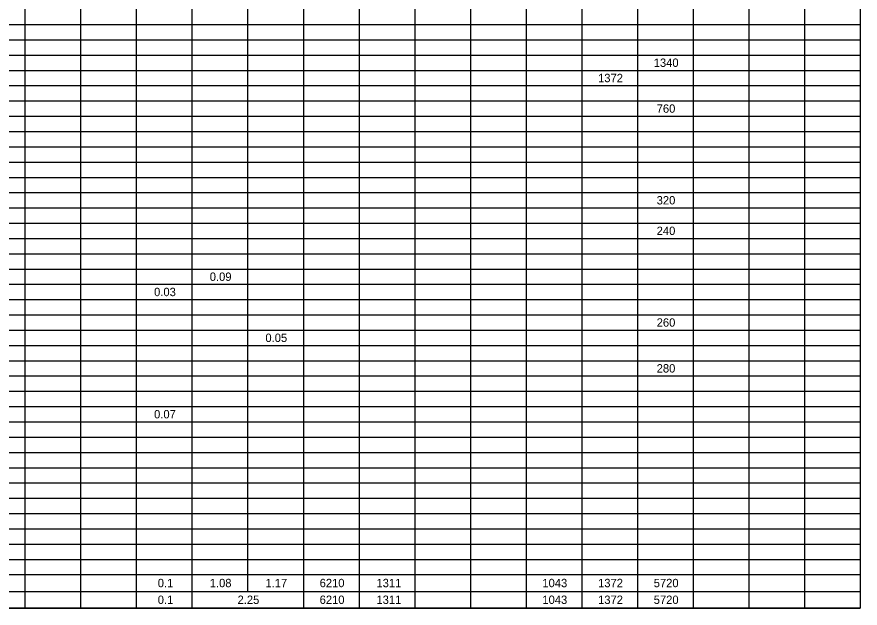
# Model space of a CAD drawing. Extents: x 91011267 to 91022583, y 37007614 to 37014266.
# Drawn here: x 91012044 to 91012802, y 37010175 to 37010707 of the extents above; entities that cross this region are included whole.
import ezdxf

# ---------------------------------------------------------------- set-up
doc = ezdxf.new("R2010")
doc.units = 0
doc.layers.add('SC_Scratch2', color=7, linetype='Continuous')
doc.layers.add('SH_Data', color=7, linetype='Continuous')

msp = doc.modelspace()

# ---------------------------------------------------------------- linework, layer by layer
at = {"layer": 'SC_Scratch2'}
msp.add_lwpolyline([(91011277.35, 37011225.45), (91012802.35, 37011225.45), (91012802.35, 37010175.45), (91011277.35, 37010175.45)], close=True, dxfattribs=at)
at = {"layer": 'SH_Data'}
for p, q in [((91012051.05, 37010851.25), (91012051.05, 37010645.17)), ((91012101.14, 37010851.25), (91012101.14, 37010645.17)), ((91012151.23, 37010851.25), (91012151.23, 37010645.17)), ((91012201.31, 37010851.25), (91012201.31, 37010645.17)), ((91012251.4, 37010851.25), (91012251.4, 37010645.17)), ((91012301.49, 37010851.25), (91012301.49, 37010645.17)), ((91012351.57, 37010851.25), (91012351.57, 37010645.17)), ((91012401.66, 37010851.25), (91012401.66, 37010645.17)), ((91012451.75, 37010851.25), (91012451.75, 37010645.17)), ((91012501.83, 37010851.25), (91012501.83, 37010645.17)), ((91012551.92, 37010851.25), (91012551.92, 37010645.17)), ((91012602, 37010851.25), (91012602, 37010645.17)), ((91012652.09, 37010851.25), (91012652.09, 37010645.17)), ((91012702.18, 37010851.25), (91012702.18, 37010645.17)), ((91012752.26, 37010851.25), (91012752.26, 37010645.17)), ((91012802.35, 37010851.25), (91012802.35, 37010645.17)), ((91012000.97, 37010700.13), (91012551.92, 37010700.13)), ((91012551.92, 37010700.13), (91012602, 37010700.13)), ((91012602, 37010700.13), (91012652.09, 37010700.13)), ((91012652.09, 37010700.13), (91012702.18, 37010700.13)), ((91012702.18, 37010700.13), (91012802.35, 37010700.13)), ((91012000.97, 37010686.39), (91012551.92, 37010686.39)), ((91012551.92, 37010686.39), (91012602, 37010686.39)), ((91012602, 37010686.39), (91012652.09, 37010686.39)), ((91012652.09, 37010686.39), (91012702.18, 37010686.39)), ((91012702.18, 37010686.39), (91012802.35, 37010686.39)), ((91012000.97, 37010672.65), (91012551.92, 37010672.65)), ((91012551.92, 37010672.65), (91012602, 37010672.65)), ((91012602, 37010672.65), (91012652.09, 37010672.65)), ((91012652.09, 37010672.65), (91012702.18, 37010672.65)), ((91012702.18, 37010672.65), (91012802.35, 37010672.65)), ((91012000.97, 37010658.91), (91012551.92, 37010658.91)), ((91012551.92, 37010658.91), (91012602, 37010658.91)), ((91012602, 37010658.91), (91012652.09, 37010658.91)), ((91012652.09, 37010658.91), (91012702.18, 37010658.91)), ((91012702.18, 37010658.91), (91012802.35, 37010658.91)), ((91012000.97, 37010645.17), (91012551.92, 37010645.17)), ((91012051.05, 37010645.17), (91012051.05, 37010631.43)), ((91012101.14, 37010645.17), (91012101.14, 37010631.43)), ((91012151.23, 37010645.17), (91012151.23, 37010631.43)), ((91012201.31, 37010645.17), (91012201.31, 37010631.43)), ((91012251.4, 37010645.17), (91012251.4, 37010631.43)), ((91012301.49, 37010645.17), (91012301.49, 37010631.43)), ((91012351.57, 37010645.17), (91012351.57, 37010631.43)), ((91012401.66, 37010645.17), (91012401.66, 37010631.43)), ((91012451.75, 37010645.17), (91012451.75, 37010631.43)), ((91012501.83, 37010645.17), (91012501.83, 37010631.43)), ((91012551.92, 37010645.17), (91012602, 37010645.17)), ((91012551.92, 37010645.17), (91012551.92, 37010631.43)), ((91012602, 37010645.17), (91012652.09, 37010645.17)), ((91012602, 37010645.17), (91012602, 37010631.43)), ((91012652.09, 37010645.17), (91012702.18, 37010645.17)), ((91012652.09, 37010645.17), (91012652.09, 37010631.43)), ((91012702.18, 37010645.17), (91012802.35, 37010645.17)), ((91012702.18, 37010645.17), (91012702.18, 37010631.43)), ((91012752.26, 37010645.17), (91012752.26, 37010631.43)), ((91012802.35, 37010645.17), (91012802.35, 37010631.43)), ((91012000.97, 37010631.43), (91012551.92, 37010631.43)), ((91012051.05, 37010631.43), (91012051.05, 37010617.7)), ((91012101.14, 37010631.43), (91012101.14, 37010617.7)), ((91012151.23, 37010631.43), (91012151.23, 37010617.7)), ((91012201.31, 37010631.43), (91012201.31, 37010617.7)), ((91012251.4, 37010631.43), (91012251.4, 37010617.7)), ((91012301.49, 37010631.43), (91012301.49, 37010617.7)), ((91012351.57, 37010631.43), (91012351.57, 37010617.7)), ((91012401.66, 37010631.43), (91012401.66, 37010617.7)), ((91012451.75, 37010631.43), (91012451.75, 37010617.7)), ((91012501.83, 37010631.43), (91012501.83, 37010617.7)), ((91012551.92, 37010631.43), (91012602, 37010631.43)), ((91012551.92, 37010631.43), (91012551.92, 37010617.7)), ((91012602, 37010631.43), (91012652.09, 37010631.43)), ((91012602, 37010631.43), (91012602, 37010617.7)), ((91012652.09, 37010631.43), (91012702.18, 37010631.43)), ((91012652.09, 37010631.43), (91012652.09, 37010617.7)), ((91012702.18, 37010631.43), (91012802.35, 37010631.43)), ((91012702.18, 37010631.43), (91012702.18, 37010617.7)), ((91012752.26, 37010631.43), (91012752.26, 37010617.7)), ((91012802.35, 37010631.43), (91012802.35, 37010617.7)), ((91012000.97, 37010617.7), (91012551.92, 37010617.7)), ((91012051.05, 37010617.7), (91012051.05, 37010576.48)), ((91012101.14, 37010617.7), (91012101.14, 37010576.48)), ((91012151.23, 37010617.7), (91012151.23, 37010576.48)), ((91012201.31, 37010617.7), (91012201.31, 37010576.48)), ((91012251.4, 37010617.7), (91012251.4, 37010576.48)), ((91012301.49, 37010617.7), (91012301.49, 37010576.48)), ((91012351.57, 37010617.7), (91012351.57, 37010576.48)), ((91012401.66, 37010617.7), (91012401.66, 37010576.48)), ((91012451.75, 37010617.7), (91012451.75, 37010576.48)), ((91012501.83, 37010617.7), (91012501.83, 37010576.48)), ((91012551.92, 37010617.7), (91012602, 37010617.7)), ((91012551.92, 37010617.7), (91012551.92, 37010576.48)), ((91012602, 37010617.7), (91012652.09, 37010617.7)), ((91012602, 37010617.7), (91012602, 37010576.48)), ((91012652.09, 37010617.7), (91012702.18, 37010617.7)), ((91012652.09, 37010617.7), (91012652.09, 37010576.48)), ((91012702.18, 37010617.7), (91012802.35, 37010617.7)), ((91012702.18, 37010617.7), (91012702.18, 37010576.48)), ((91012752.26, 37010617.7), (91012752.26, 37010576.48)), ((91012802.35, 37010617.7), (91012802.35, 37010576.48)), ((91012000.97, 37010603.96), (91012551.92, 37010603.96)), ((91012551.92, 37010603.96), (91012602, 37010603.96)), ((91012602, 37010603.96), (91012652.09, 37010603.96)), ((91012652.09, 37010603.96), (91012702.18, 37010603.96)), ((91012702.18, 37010603.96), (91012802.35, 37010603.96)), ((91012000.97, 37010590.22), (91012551.92, 37010590.22)), ((91012551.92, 37010590.22), (91012602, 37010590.22)), ((91012602, 37010590.22), (91012652.09, 37010590.22)), ((91012652.09, 37010590.22), (91012702.18, 37010590.22)), ((91012702.18, 37010590.22), (91012802.35, 37010590.22)), ((91012000.97, 37010576.48), (91012551.92, 37010576.48)), ((91012051.05, 37010576.48), (91012051.05, 37010562.74)), ((91012101.14, 37010576.48), (91012101.14, 37010562.74)), ((91012151.23, 37010576.48), (91012151.23, 37010562.74)), ((91012201.31, 37010576.48), (91012201.31, 37010562.74)), ((91012251.4, 37010576.48), (91012251.4, 37010562.74)), ((91012301.49, 37010576.48), (91012301.49, 37010562.74)), ((91012351.57, 37010576.48), (91012351.57, 37010562.74)), ((91012401.66, 37010576.48), (91012401.66, 37010562.74)), ((91012451.75, 37010576.48), (91012451.75, 37010562.74)), ((91012501.83, 37010576.48), (91012501.83, 37010562.74)), ((91012551.92, 37010576.48), (91012602, 37010576.48)), ((91012551.92, 37010576.48), (91012551.92, 37010562.74)), ((91012602, 37010576.48), (91012652.09, 37010576.48)), ((91012602, 37010576.48), (91012602, 37010562.74)), ((91012652.09, 37010576.48), (91012702.18, 37010576.48)), ((91012652.09, 37010576.48), (91012652.09, 37010562.74)), ((91012702.18, 37010576.48), (91012802.35, 37010576.48)), ((91012702.18, 37010576.48), (91012702.18, 37010562.74)), ((91012752.26, 37010576.48), (91012752.26, 37010562.74)), ((91012802.35, 37010576.48), (91012802.35, 37010562.74)), ((91012000.97, 37010562.74), (91012551.92, 37010562.74)), ((91012051.05, 37010562.74), (91012051.05, 37010549)), ((91012101.14, 37010562.74), (91012101.14, 37010549)), ((91012151.23, 37010562.74), (91012151.23, 37010549)), ((91012201.31, 37010562.74), (91012201.31, 37010549)), ((91012251.4, 37010562.74), (91012251.4, 37010549)), ((91012301.49, 37010562.74), (91012301.49, 37010549)), ((91012351.57, 37010562.74), (91012351.57, 37010549)), ((91012401.66, 37010562.74), (91012401.66, 37010549)), ((91012451.75, 37010562.74), (91012451.75, 37010549)), ((91012501.83, 37010562.74), (91012501.83, 37010549)), ((91012551.92, 37010562.74), (91012602, 37010562.74)), ((91012551.92, 37010562.74), (91012551.92, 37010549)), ((91012602, 37010562.74), (91012652.09, 37010562.74)), ((91012602, 37010562.74), (91012602, 37010549)), ((91012652.09, 37010562.74), (91012702.18, 37010562.74)), ((91012652.09, 37010562.74), (91012652.09, 37010549)), ((91012702.18, 37010562.74), (91012802.35, 37010562.74)), ((91012702.18, 37010562.74), (91012702.18, 37010549)), ((91012752.26, 37010562.74), (91012752.26, 37010549)), ((91012802.35, 37010562.74), (91012802.35, 37010549)), ((91012000.97, 37010549), (91012551.92, 37010549)), ((91012051.05, 37010549), (91012051.05, 37010507.79)), ((91012101.14, 37010549), (91012101.14, 37010507.79)), ((91012151.23, 37010549), (91012151.23, 37010507.79)), ((91012201.31, 37010549), (91012201.31, 37010507.79)), ((91012251.4, 37010549), (91012251.4, 37010507.79)), ((91012301.49, 37010549), (91012301.49, 37010507.79)), ((91012351.57, 37010549), (91012351.57, 37010507.79)), ((91012401.66, 37010549), (91012401.66, 37010507.79)), ((91012451.75, 37010549), (91012451.75, 37010507.79)), ((91012501.83, 37010549), (91012501.83, 37010507.79)), ((91012551.92, 37010549), (91012602, 37010549)), ((91012551.92, 37010549), (91012551.92, 37010507.79)), ((91012602, 37010549), (91012652.09, 37010549)), ((91012602, 37010549), (91012602, 37010507.79)), ((91012652.09, 37010549), (91012702.18, 37010549)), ((91012652.09, 37010549), (91012652.09, 37010507.79)), ((91012702.18, 37010549), (91012802.35, 37010549)), ((91012702.18, 37010549), (91012702.18, 37010507.79)), ((91012752.26, 37010549), (91012752.26, 37010507.79)), ((91012802.35, 37010549), (91012802.35, 37010507.79)), ((91012000.97, 37010535.27), (91012551.92, 37010535.27)), ((91012551.92, 37010535.27), (91012602, 37010535.27)), ((91012602, 37010535.27), (91012652.09, 37010535.27)), ((91012652.09, 37010535.27), (91012702.18, 37010535.27)), ((91012702.18, 37010535.27), (91012802.35, 37010535.27)), ((91012000.97, 37010521.53), (91012551.92, 37010521.53)), ((91012551.92, 37010521.53), (91012602, 37010521.53)), ((91012602, 37010521.53), (91012652.09, 37010521.53)), ((91012652.09, 37010521.53), (91012702.18, 37010521.53)), ((91012702.18, 37010521.53), (91012802.35, 37010521.53)), ((91012000.97, 37010507.79), (91012551.92, 37010507.79)), ((91012051.05, 37010507.79), (91012051.05, 37010494.05)), ((91012101.14, 37010507.79), (91012101.14, 37010494.05)), ((91012151.23, 37010507.79), (91012151.23, 37010494.05)), ((91012201.31, 37010507.79), (91012201.31, 37010494.05)), ((91012251.4, 37010507.79), (91012251.4, 37010494.05)), ((91012301.49, 37010507.79), (91012301.49, 37010494.05)), ((91012351.57, 37010507.79), (91012351.57, 37010494.05)), ((91012401.66, 37010507.79), (91012401.66, 37010494.05)), ((91012451.75, 37010507.79), (91012451.75, 37010494.05)), ((91012501.83, 37010507.79), (91012501.83, 37010494.05)), ((91012551.92, 37010507.79), (91012602, 37010507.79)), ((91012551.92, 37010507.79), (91012551.92, 37010494.05)), ((91012602, 37010507.79), (91012652.09, 37010507.79)), ((91012602, 37010507.79), (91012602, 37010494.05)), ((91012652.09, 37010507.79), (91012702.18, 37010507.79)), ((91012652.09, 37010507.79), (91012652.09, 37010494.05)), ((91012702.18, 37010507.79), (91012802.35, 37010507.79)), ((91012702.18, 37010507.79), (91012702.18, 37010494.05)), ((91012752.26, 37010507.79), (91012752.26, 37010494.05)), ((91012802.35, 37010507.79), (91012802.35, 37010494.05)), ((91012000.97, 37010494.05), (91012551.92, 37010494.05)), ((91012051.05, 37010494.05), (91012051.05, 37010480.31)), ((91012101.14, 37010494.05), (91012101.14, 37010480.31)), ((91012151.23, 37010494.05), (91012151.23, 37010480.31)), ((91012201.31, 37010494.05), (91012201.31, 37010480.31)), ((91012251.4, 37010494.05), (91012251.4, 37010480.31)), ((91012301.49, 37010494.05), (91012301.49, 37010480.31)), ((91012351.57, 37010494.05), (91012351.57, 37010480.31)), ((91012401.66, 37010494.05), (91012401.66, 37010480.31)), ((91012451.75, 37010494.05), (91012451.75, 37010480.31)), ((91012501.83, 37010494.05), (91012501.83, 37010480.31)), ((91012551.92, 37010494.05), (91012602, 37010494.05)), ((91012551.92, 37010494.05), (91012551.92, 37010480.31)), ((91012602, 37010494.05), (91012652.09, 37010494.05)), ((91012602, 37010494.05), (91012602, 37010480.31)), ((91012652.09, 37010494.05), (91012702.18, 37010494.05)), ((91012652.09, 37010494.05), (91012652.09, 37010480.31)), ((91012702.18, 37010494.05), (91012802.35, 37010494.05)), ((91012702.18, 37010494.05), (91012702.18, 37010480.31)), ((91012752.26, 37010494.05), (91012752.26, 37010480.31)), ((91012802.35, 37010494.05), (91012802.35, 37010480.31)), ((91012000.97, 37010480.31), (91012551.92, 37010480.31)), ((91012051.05, 37010480.31), (91012051.05, 37010175.45)), ((91012101.14, 37010480.31), (91012101.14, 37010175.45)), ((91012151.23, 37010480.31), (91012151.23, 37010175.45)), ((91012201.31, 37010480.31), (91012201.31, 37010175.45)), ((91012251.4, 37010480.31), (91012251.4, 37010190.5)), ((91012301.49, 37010480.31), (91012301.49, 37010175.45)), ((91012351.57, 37010480.31), (91012351.57, 37010175.45)), ((91012401.66, 37010480.31), (91012401.66, 37010175.45)), ((91012451.75, 37010480.31), (91012451.75, 37010175.45)), ((91012501.83, 37010480.31), (91012501.83, 37010175.45)), ((91012551.92, 37010480.31), (91012602, 37010480.31)), ((91012551.92, 37010480.31), (91012551.92, 37010175.45)), ((91012602, 37010480.31), (91012652.09, 37010480.31)), ((91012602, 37010480.31), (91012602, 37010175.45)), ((91012652.09, 37010480.31), (91012702.18, 37010480.31)), ((91012652.09, 37010480.31), (91012652.09, 37010175.45)), ((91012702.18, 37010480.31), (91012802.35, 37010480.31)), ((91012702.18, 37010480.31), (91012702.18, 37010175.45)), ((91012752.26, 37010480.31), (91012752.26, 37010175.45)), ((91012802.35, 37010480.31), (91012802.35, 37010175.45)), ((91012000.97, 37010466.57), (91012551.92, 37010466.57)), ((91012551.92, 37010466.57), (91012602, 37010466.57)), ((91012602, 37010466.57), (91012652.09, 37010466.57)), ((91012652.09, 37010466.57), (91012702.18, 37010466.57)), ((91012702.18, 37010466.57), (91012802.35, 37010466.57)), ((91012000.97, 37010452.84), (91012551.92, 37010452.84)), ((91012551.92, 37010452.84), (91012602, 37010452.84)), ((91012602, 37010452.84), (91012652.09, 37010452.84)), ((91012652.09, 37010452.84), (91012702.18, 37010452.84)), ((91012702.18, 37010452.84), (91012802.35, 37010452.84)), ((91012000.97, 37010439.1), (91012551.92, 37010439.1)), ((91012551.92, 37010439.1), (91012602, 37010439.1)), ((91012602, 37010439.1), (91012652.09, 37010439.1)), ((91012652.09, 37010439.1), (91012702.18, 37010439.1)), ((91012702.18, 37010439.1), (91012802.35, 37010439.1)), ((91012000.97, 37010425.36), (91012551.92, 37010425.36)), ((91012551.92, 37010425.36), (91012602, 37010425.36)), ((91012602, 37010425.36), (91012652.09, 37010425.36)), ((91012652.09, 37010425.36), (91012702.18, 37010425.36)), ((91012702.18, 37010425.36), (91012802.35, 37010425.36)), ((91012000.97, 37010411.62), (91012551.92, 37010411.62)), ((91012551.92, 37010411.62), (91012602, 37010411.62)), ((91012602, 37010411.62), (91012652.09, 37010411.62)), ((91012652.09, 37010411.62), (91012702.18, 37010411.62)), ((91012702.18, 37010411.62), (91012802.35, 37010411.62)), ((91012000.97, 37010397.88), (91012551.92, 37010397.88)), ((91012551.92, 37010397.88), (91012602, 37010397.88)), ((91012602, 37010397.88), (91012652.09, 37010397.88)), ((91012652.09, 37010397.88), (91012702.18, 37010397.88)), ((91012702.18, 37010397.88), (91012802.35, 37010397.88)), ((91012000.97, 37010384.14), (91012551.92, 37010384.14)), ((91012551.92, 37010384.14), (91012602, 37010384.14)), ((91012602, 37010384.14), (91012652.09, 37010384.14)), ((91012652.09, 37010384.14), (91012702.18, 37010384.14)), ((91012702.18, 37010384.14), (91012802.35, 37010384.14)), ((91012000.97, 37010370.41), (91012551.92, 37010370.41)), ((91012551.92, 37010370.41), (91012602, 37010370.41)), ((91012602, 37010370.41), (91012652.09, 37010370.41)), ((91012652.09, 37010370.41), (91012702.18, 37010370.41)), ((91012702.18, 37010370.41), (91012802.35, 37010370.41)), ((91012000.97, 37010356.67), (91012551.92, 37010356.67)), ((91012551.92, 37010356.67), (91012602, 37010356.67)), ((91012602, 37010356.67), (91012652.09, 37010356.67)), ((91012652.09, 37010356.67), (91012702.18, 37010356.67)), ((91012702.18, 37010356.67), (91012802.35, 37010356.67)), ((91012000.97, 37010342.93), (91012551.92, 37010342.93)), ((91012551.92, 37010342.93), (91012602, 37010342.93)), ((91012602, 37010342.93), (91012652.09, 37010342.93)), ((91012652.09, 37010342.93), (91012702.18, 37010342.93)), ((91012702.18, 37010342.93), (91012802.35, 37010342.93)), ((91012000.97, 37010329.19), (91012551.92, 37010329.19)), ((91012551.92, 37010329.19), (91012602, 37010329.19)), ((91012602, 37010329.19), (91012652.09, 37010329.19)), ((91012652.09, 37010329.19), (91012702.18, 37010329.19)), ((91012702.18, 37010329.19), (91012802.35, 37010329.19)), ((91012000.97, 37010315.45), (91012551.92, 37010315.45)), ((91012551.92, 37010315.45), (91012602, 37010315.45)), ((91012602, 37010315.45), (91012652.09, 37010315.45)), ((91012652.09, 37010315.45), (91012702.18, 37010315.45)), ((91012702.18, 37010315.45), (91012802.35, 37010315.45)), ((91012000.97, 37010301.71), (91012551.92, 37010301.71)), ((91012551.92, 37010301.71), (91012602, 37010301.71)), ((91012602, 37010301.71), (91012652.09, 37010301.71)), ((91012652.09, 37010301.71), (91012702.18, 37010301.71)), ((91012702.18, 37010301.71), (91012802.35, 37010301.71)), ((91012000.97, 37010287.98), (91012551.92, 37010287.98)), ((91012551.92, 37010287.98), (91012602, 37010287.98)), ((91012602, 37010287.98), (91012652.09, 37010287.98)), ((91012652.09, 37010287.98), (91012702.18, 37010287.98)), ((91012702.18, 37010287.98), (91012802.35, 37010287.98)), ((91012000.97, 37010274.24), (91012551.92, 37010274.24)), ((91012551.92, 37010274.24), (91012602, 37010274.24)), ((91012602, 37010274.24), (91012652.09, 37010274.24)), ((91012652.09, 37010274.24), (91012702.18, 37010274.24)), ((91012702.18, 37010274.24), (91012802.35, 37010274.24)), ((91012000.97, 37010260.5), (91012551.92, 37010260.5)), ((91012551.92, 37010260.5), (91012602, 37010260.5)), ((91012602, 37010260.5), (91012652.09, 37010260.5)), ((91012652.09, 37010260.5), (91012702.18, 37010260.5)), ((91012702.18, 37010260.5), (91012802.35, 37010260.5)), ((91012000.97, 37010246.76), (91012551.92, 37010246.76)), ((91012551.92, 37010246.76), (91012602, 37010246.76)), ((91012602, 37010246.76), (91012652.09, 37010246.76)), ((91012652.09, 37010246.76), (91012702.18, 37010246.76)), ((91012702.18, 37010246.76), (91012802.35, 37010246.76)), ((91012000.97, 37010233.02), (91012551.92, 37010233.02)), ((91012551.92, 37010233.02), (91012602, 37010233.02)), ((91012602, 37010233.02), (91012652.09, 37010233.02)), ((91012652.09, 37010233.02), (91012702.18, 37010233.02)), ((91012702.18, 37010233.02), (91012802.35, 37010233.02)), ((91012000.97, 37010219.29), (91012551.92, 37010219.29)), ((91012551.92, 37010219.29), (91012602, 37010219.29)), ((91012602, 37010219.29), (91012652.09, 37010219.29)), ((91012652.09, 37010219.29), (91012702.18, 37010219.29)), ((91012702.18, 37010219.29), (91012802.35, 37010219.29)), ((91012000.97, 37010205.55), (91012551.92, 37010205.55)), ((91012551.92, 37010205.55), (91012602, 37010205.55)), ((91012602, 37010205.55), (91012652.09, 37010205.55)), ((91012652.09, 37010205.55), (91012702.18, 37010205.55)), ((91012702.18, 37010205.55), (91012802.35, 37010205.55)), ((91012000.97, 37010190.5), (91012551.92, 37010190.5)), ((91012551.92, 37010190.5), (91012602, 37010190.5)), ((91012602, 37010190.5), (91012652.09, 37010190.5)), ((91012652.09, 37010190.5), (91012702.18, 37010190.5)), ((91012702.18, 37010190.5), (91012802.35, 37010190.5)), ((91012000.97, 37010175.45), (91012551.92, 37010175.45)), ((91012551.92, 37010175.45), (91012602, 37010175.45)), ((91012602, 37010175.45), (91012652.09, 37010175.45)), ((91012652.09, 37010175.45), (91012702.18, 37010175.45)), ((91012702.18, 37010175.45), (91012802.35, 37010175.45))]:
    msp.add_line(p, q, dxfattribs=at)

# ---------------------------------------------------------------- texts
for s, p in [('1340', (91012616.68, 37010662.02)), ('1372', (91012566.62, 37010648.28)), ('760', (91012619.33, 37010620.8)), ('320', (91012619.33, 37010538.37)), ('240', (91012619.33, 37010510.9)), ('0.09', (91012217.3, 37010469.68)), ('0.03', (91012167.22, 37010455.94)), ('260', (91012619.33, 37010428.47)), ('0.05', (91012267.36, 37010414.73)), ('280', (91012619.33, 37010387.25)), ('0.07', (91012167.22, 37010346.04)), ('0.1', (91012170.52, 37010194.26)), ('1.08', (91012217.3, 37010194.26)), ('1.17', (91012267.39, 37010194.26)), ('6210', (91012316.16, 37010194.26)), ('1311', (91012367.25, 37010194.26)), ('1043', (91012516.5, 37010194.26)), ('1372', (91012566.62, 37010194.26)), ('5720', (91012616.68, 37010194.26)), ('0.1', (91012170.52, 37010179.21)), ('2.25', (91012242.32, 37010179.21)), ('6210', (91012316.16, 37010179.21)), ('1311', (91012367.25, 37010179.21)), ('1043', (91012516.5, 37010179.21)), ('1372', (91012566.62, 37010179.21)), ('5720', (91012616.68, 37010179.21))]:
    msp.add_text(s, height=7.523, dxfattribs=at).set_placement(p)

doc.saveas('drawing.dxf')
